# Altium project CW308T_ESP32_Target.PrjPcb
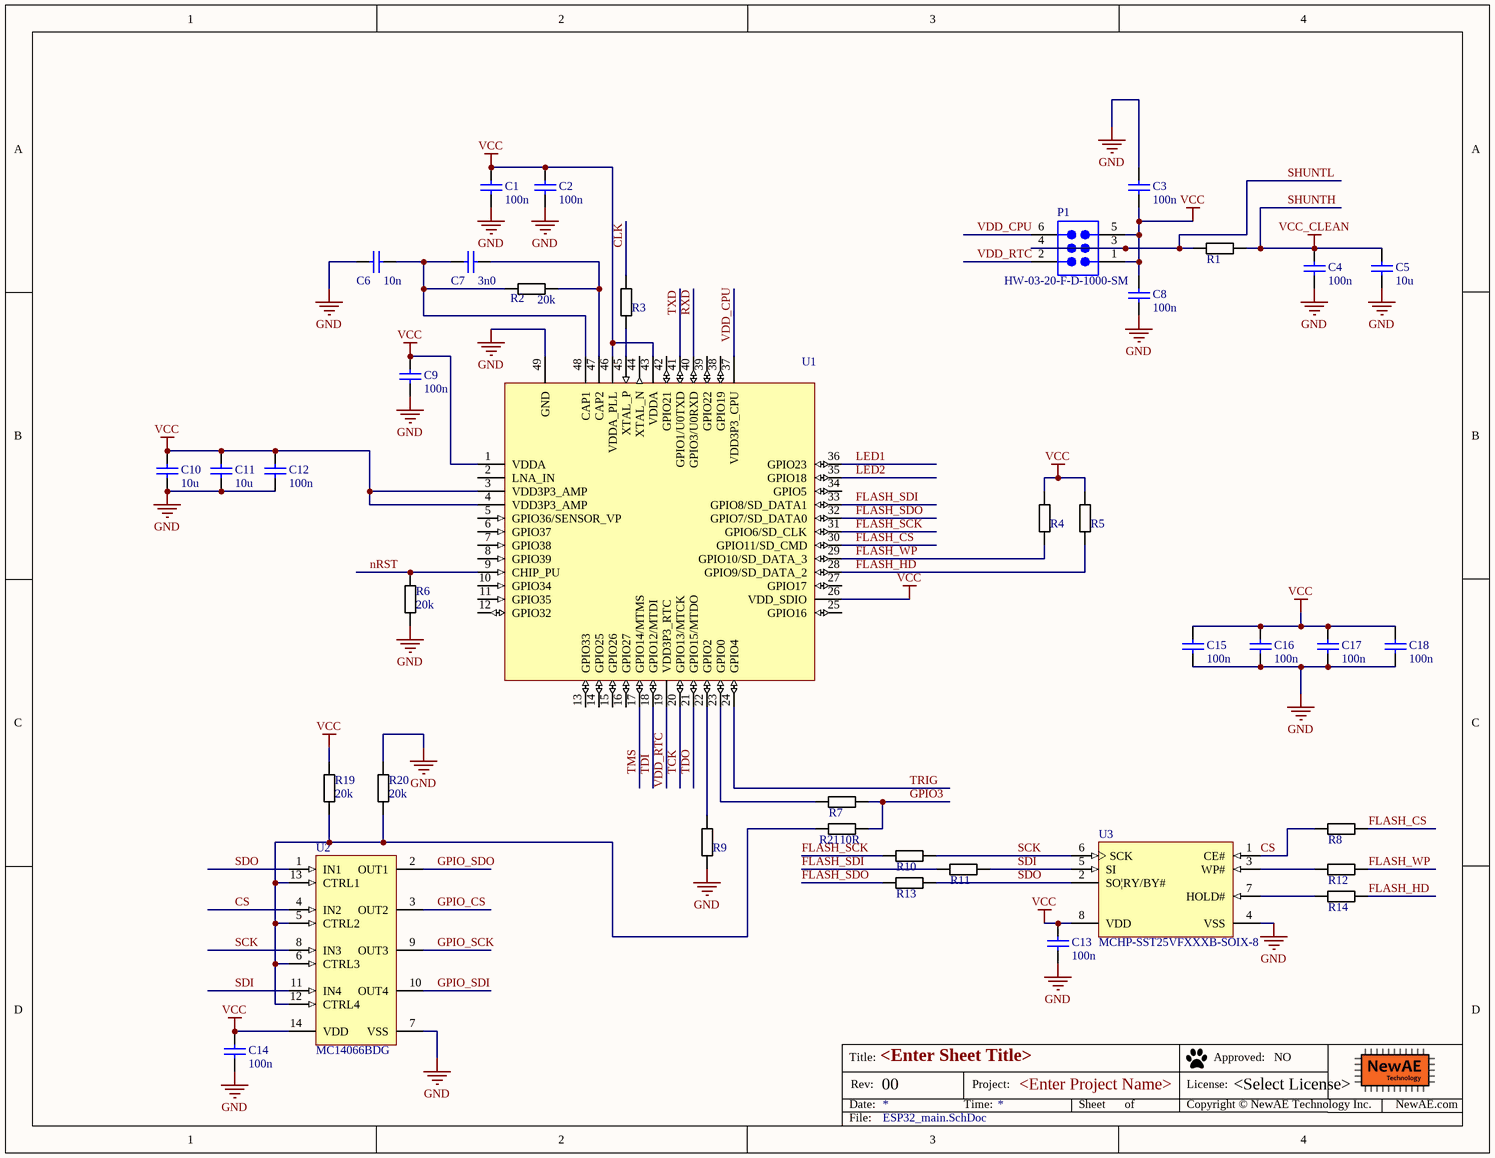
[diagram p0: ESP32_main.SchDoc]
PrjLicense: <Select License>; PrjName: <Enter Project Name>; PrjRev: 00
2 sheets, 44 parts. Net scope: global (net labels, ports and power ports of the same name join across sheets).
Sheets:
  ESP32_main.SchDoc
  ESP32_cw.SchDoc

## Sheet ESP32_main.SchDoc: <Enter Sheet Title>
size Letter; Organization: NewAE Technology Inc.; Address1: 1083 Queen St., Suite 196; Address2: Halifax; Address3: NS; Address4: Canada B3H 0B2; SheetApproved: NO

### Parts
C1  100n  [CAPC0603_M]  (value not drawn)
C2  100n  [CAPC0603_M]  (value not drawn)
C3  100n  [CAPC0603_M]  (value not drawn)
C4  100n  [CAPC0603_M]  (value not drawn)
C5  10u  [CAPC0603_M]  (value not drawn)
C6  10n  [CAPC0603_M]
C7  3n0  [CAPC0603_M]
C8  100n  [CAPC0603_M]  (value not drawn)
C9  100n  [CAPC0603_M]  (value not drawn)
C10  10u  [CAPC0603_M]  (value not drawn)
C11  10u  [CAPC0603_M]  (value not drawn)
C12  100n  [CAPC0603_M]  (value not drawn)
C13  100n  [CAPC0603_M]  (value not drawn)
C14  100n  [CAPC0603_M]  (value not drawn)
C15  100n  [CAPC0603_M]  (value not drawn)
C16  100n  [CAPC0603_M]  (value not drawn)
C17  100n  [CAPC0603_M]  (value not drawn)
C18  100n  [CAPC0603_M]  (value not drawn)
P1  HW-03-20-F-D-1000-SM  [SMTC-HW-03-20-X-D-1000-SM]
R1  4R7  [RESC1608X55N]  (value not drawn)
R2  20k  [RESC1608X55N]
R3  51R  [RESC1608X55N]  (value not drawn)
R4  20k  [RESC1608X55N]  (value not drawn)
R5  20k  [RESC1608X55N]  (value not drawn)
R6  20k  [RESC1608X55N]
R7  10R  [RESC1608X55N]  (value not drawn)
R8  10R  [RESC1608X55N]  (value not drawn)
R9  20k  [RESC1608X55N]  (value not drawn)
R10  10R  [RESC1608X55N]  (value not drawn)
R11  10R  [RESC1608X55N]  (value not drawn)
R12  10R  [RESC1608X55N]  (value not drawn)
R13  10R  [RESC1608X55N]  (value not drawn)
R14  10R  [RESC1608X55N]  (value not drawn)
R19  20k  [RESC1608X55N]
R20  20k  [RESC1608X55N]
R21  10R  [RESC1608X55N]
U1  ESP32  [QFN48_6x6_0.4mm_HANDSOLDERING]  (value not drawn)
U2  MC14066BDG  [ONSC-SOIC-14-751A-03_V]
U3  MCHP-SST25VFXXXB-SOIX-8  [SOIC8_NARROW]

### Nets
GND: C1.2 C2.2 C3.1 C4.2 C5.2 C6.1 C8.2 C9.2 C10.2 C11.2 C12.2 C13.2 C14.2 C15.2 C16.2 C17.2 C18.2 R6.1 R9.2 R20.2 U1.49(GND) U2.7(VSS) U3.4(VSS)
SHUNTH: C4.1 C5.1 R1.2  [also labelled VCC_CLEAN]
VCC: C1.1 C2.1 C3.2 C8.1 C9.1 C10.1 C11.1 C12.1 C13.1 C14.1 C15.1 C16.1 C17.1 C18.1 P1.1 P1.5 R4.1 R5.1 R19.2 U1.1(VDDA) U1.3(VDD3P3_AMP) U1.4(VDD3P3_AMP) U1.26(VDD_SDIO) U1.43(VDDA) U1.46(VDDA_PLL) U2.14(VDD) U3.8(VDD)
CLK: R3.1
CS: R8.1 U2.4(IN2) U3.1(CE#)
FLASH_CS: R8.2 U1.30(GPIO11/SD_CMD)
FLASH_HD: R5.2 R14.2 U1.28(GPIO9/SD_DATA_2)
FLASH_SCK: R10.1 U1.31(GPIO6/SD_CLK)
FLASH_SDI: R11.1 U1.33(GPIO8/SD_DATA1)
FLASH_SDO: R13.1 U1.32(GPIO7/SD_DATA0)
FLASH_WP: R4.2 R12.2 U1.29(GPIO10/SD_DATA_3)
GPIO3: R7.2 R21.2
GPIO_CS: U2.3(OUT2)
GPIO_SCK: U2.9(OUT3)
GPIO_SDI: U2.10(OUT4)
GPIO_SDO: U2.2(OUT1)
LED1: U1.36(GPIO23)
LED2: U1.35(GPIO18)
nRST: R6.2 U1.9(CHIP_PU)
RXD: U1.40(GPIO3/U0RXD)
SCK: R10.2 U2.8(IN3) U3.6(SCK)
SDI: R11.2 U2.11(IN4) U3.5(SI)
SDO: R13.2 U2.1(IN1) U3.2(SO¦RY/BY#)
SHUNTL: P1.3 P1.4 R1.1
TCK: U1.20(GPIO13/MTCK)
TDI: U1.18(GPIO12/MTDI)
TDO: U1.21(GPIO15/MTDO)
TMS: U1.17(GPIO14/MTMS)
TRIG: U1.24(GPIO4)
TXD: U1.41(GPIO1/U0TXD)
VDD_CPU: P1.6 U1.37(VDD3P3_CPU)
VDD_RTC: P1.2 U1.19(VDD3P3_RTC)
NetC6_2: C6.2 C7.1 R2.1 U1.48(CAP1)
NetC7_2: C7.2 R2.2 U1.47(CAP2)
NetR3_2: R3.2 U1.45(XTAL_P)
NetR7_1: R7.1 U1.23(GPIO0)
NetR9_1: R9.1 U1.22(GPIO2)
NetR12_1: R12.1 U3.3(WP#)
NetR14_1: R14.1 U3.7(HOLD#)
NetR19_1: R19.1 R20.1 R21.1 U2.5(CTRL2) U2.6(CTRL3) U2.12(CTRL4) U2.13(CTRL1)

Not connected (* = marked no-connect by the designer): U1 2(LNA_IN) 5(GPIO36/SENSOR_VP) 6(GPIO37) 7(GPIO38) 8(GPIO39) 10(GPIO34) 11(GPIO35) 12(GPIO32) 13(GPIO33) 14(GPIO25) 15(GPIO26) 16(GPIO27) 25(GPIO16) 27(GPIO17) 34(GPIO5) 38(GPIO19) 39(GPIO22) 42(GPIO21) 44(XTAL_N)

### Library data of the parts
C1-C4 C8 C9 C12-C18 = CCHIP-100n-0603: 100n, 0603; Case-EIA: 0603; Case-Metric: 1608
C5 C10 C11 = CCHIP-10u-0603: 10u, 0603; Case-EIA: 0603; Case-Metric: 1608
C6 = CCHIP-10n-0603: 10n, 0603; Case-EIA: 0603; Case-Metric: 1608
C7 = CCHIP-3n0-0603: 3n0, 0603; Case-EIA: 0603; Case-Metric: 1608
P1 = CMP-1025-00031-1: Manufacturer: Samtec; Pitch: 2.54 mm
R1 = RCHIP-4R7-0603: 4R7 res, 0603, 1%, 1/10W; Manufacture 1: Yageo; Manufacture Part Number 1: RC0603FR-074R7L; Case-EIA: 0603; Case-Metric: 1608; Rated Power: 0.1W; Rated Voltage: 75VDC
R2 R4-R6 R9 R19 R20 = RCHIP-20K-0603: 20k res, 0603, 1%, 1/10W; Manufacture 1: Yageo; Manufacture Part Number 1: RC0603FR-0720KL; Case-EIA: 0603; Case-Metric: 1608; Rated Power: 0.1W; Rated Voltage: 75VDC
R3 = RCHIP-51R-0603: 51R res, 0603, 1%, 1/10W; Manufacture 1: Yageo; Manufacture Part Number 1: RC0603FR-0751RL; Case-EIA: 0603; Case-Metric: 1608; Rated Power: 0.1W; Rated Voltage: 75VDC
R7 R8 R10-R14 R21 = RCHIP-10R-0603: 10R res, 0603, 1%, 1/10W; Manufacture 1: Yageo; Manufacture Part Number 1: RC0603FR-0710RL; Case-EIA: 0603; Case-Metric: 1608; Rated Power: 0.1W; Rated Voltage: 75VDC
U1 = ESP32: Dual-Core WiFi/Bluetooth Chip
U2 = CMP-1307-00073-1: Quad Analog Switch / Quad Multiplexer, 3 to 18 V, -55 to 125 degC, 14-Pin SOIC, Pb-Free, Tube; Manufacturer: On Semiconductor; VCC Min (V): 3; Icc Max (uA): 30; VCC Max (V): 18
U3 = SPI-FLASH-NARROW

## Sheet ESP32_cw.SchDoc: <Enter Sheet Title>
size Letter; Organization: NewAE Technology Inc.; Address1: 1083 Queen St., Suite 196; Address2: Halifax; Address3: NS; Address4: Canada B3H 0B2; SheetApproved: NO
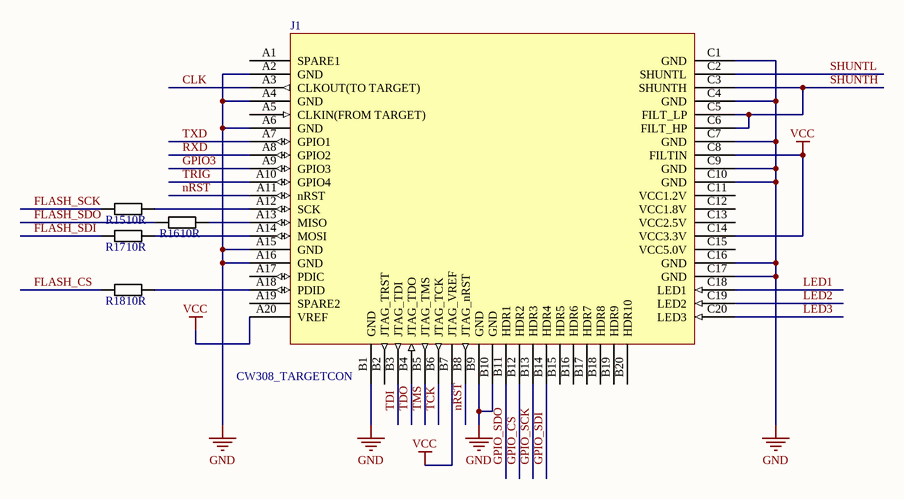
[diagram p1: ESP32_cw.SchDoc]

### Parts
J1  CW308_TARGETCON  [CW308_TBOARD_CONN]
R15  10R  [RESC1608X55N]
R16  10R  [RESC1608X55N]
R17  10R  [RESC1608X55N]
R18  10R  [RESC1608X55N]

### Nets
GND: J1.A2(GND) J1.A4(GND) J1.A6(GND) J1.A15(GND) J1.A16(GND) J1.B1(GND) J1.B9(GND) J1.B10(GND) J1.C1(GND) J1.C4(GND) J1.C7(GND) J1.C9(GND) J1.C10(GND) J1.C16(GND) J1.C17(GND)
SHUNTH: J1.C3(SHUNTH) J1.C5(FILT_LP) J1.C6(FILT_HP)
VCC: J1.A20(VREF) J1.B7(JTAG_VREF) J1.C8(FILTIN) J1.C14(VCC3.3V)
CLK: J1.A3(CLKOUT(TO_TARGET))
FLASH_CS: R18.1
FLASH_SCK: R15.1
FLASH_SDI: R17.1
FLASH_SDO: R16.1
GPIO3: J1.A9(GPIO3)
GPIO_CS: J1.B12(HDR2)
GPIO_SCK: J1.B13(HDR3)
GPIO_SDI: J1.B14(HDR4)
GPIO_SDO: J1.B11(HDR1)
LED1: J1.C18(LED1)
LED2: J1.C19(LED2)
LED3: J1.C20(LED3)
nRST: J1.A11(nRST) J1.B8(JTAG_nRST)
RXD: J1.A8(GPIO2)
SHUNTL: J1.C2(SHUNTL)
TCK: J1.B6(JTAG_TCK)
TDI: J1.B3(JTAG_TDI)
TDO: J1.B4(JTAG_TDO)
TMS: J1.B5(JTAG_TMS)
TRIG: J1.A10(GPIO4)
TXD: J1.A7(GPIO1)
NetJ1_A12: J1.A12(SCK) R15.2
NetJ1_A13: J1.A13(MISO) R16.2
NetJ1_A14: J1.A14(MOSI) R17.2
NetJ1_A18: J1.A18(PDID) R18.2

Not connected (* = marked no-connect by the designer): J1 A1(SPARE1) A5(CLKIN(FROM_TARGET)) A17(PDIC) A19(SPARE2) B2(JTAG_TRST) B15(HDR5) B16(HDR6) B17(HDR7) B18(HDR8) B19(HDR9) B20(HDR10) C11(VCC1.2V) C12(VCC1.8V) C13(VCC2.5V) C15(VCC5.0V)

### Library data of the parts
J1 = CW308_TBOARD: CW308 "Standard" Target Board Connector; Pitch: 2.54mm
R15-R18 = RCHIP-10R-0603: as R7 on sheet ESP32_main

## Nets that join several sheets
GND: ESP32_main (23 pins), ESP32_cw (15 pins)
SHUNTH: ESP32_main (C4.1 C5.1 R1.2), ESP32_cw (J1.C3 J1.C5 J1.C6)
VCC: ESP32_main (27 pins), ESP32_cw (J1.A20 J1.B7 J1.C8 J1.C14)
CLK: ESP32_main (R3.1), ESP32_cw (J1.A3)
FLASH_CS: ESP32_main (R8.2 U1.30), ESP32_cw (R18.1)
FLASH_SCK: ESP32_main (R10.1 U1.31), ESP32_cw (R15.1)
FLASH_SDI: ESP32_main (R11.1 U1.33), ESP32_cw (R17.1)
FLASH_SDO: ESP32_main (R13.1 U1.32), ESP32_cw (R16.1)
GPIO3: ESP32_main (R7.2 R21.2), ESP32_cw (J1.A9)
GPIO_CS: ESP32_main (U2.3), ESP32_cw (J1.B12)
GPIO_SCK: ESP32_main (U2.9), ESP32_cw (J1.B13)
GPIO_SDI: ESP32_main (U2.10), ESP32_cw (J1.B14)
GPIO_SDO: ESP32_main (U2.2), ESP32_cw (J1.B11)
LED1: ESP32_main (U1.36), ESP32_cw (J1.C18)
LED2: ESP32_main (U1.35), ESP32_cw (J1.C19)
nRST: ESP32_main (R6.2 U1.9), ESP32_cw (J1.A11 J1.B8)
RXD: ESP32_main (U1.40), ESP32_cw (J1.A8)
SHUNTL: ESP32_main (P1.3 P1.4 R1.1), ESP32_cw (J1.C2)
TCK: ESP32_main (U1.20), ESP32_cw (J1.B6)
TDI: ESP32_main (U1.18), ESP32_cw (J1.B3)
TDO: ESP32_main (U1.21), ESP32_cw (J1.B4)
TMS: ESP32_main (U1.17), ESP32_cw (J1.B5)
TRIG: ESP32_main (U1.24), ESP32_cw (J1.A10)
TXD: ESP32_main (U1.41), ESP32_cw (J1.A7)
